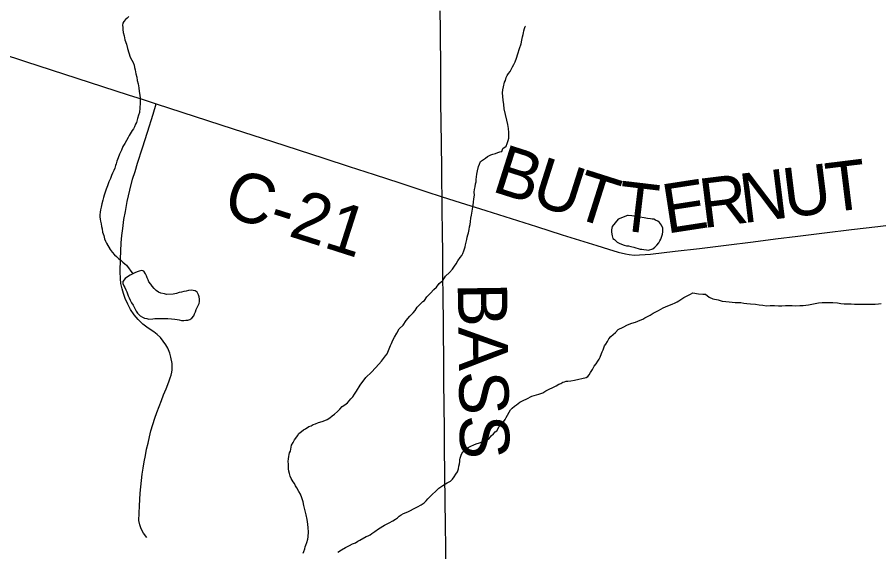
# Model space of a CAD drawing. Extents: x 103424 to 286016, y 38711 to 110967.
# Drawn here: x 139139 to 144407, y 67287 to 70553 of the extents above; entities that cross this region are included whole.
import ezdxf

# ---------------------------------------------------------------- set-up
doc = ezdxf.new("R2010")
doc.units = 0
for name, color, linetype in [('GM_X_County_Road', 7, 'Continuous'), ('GM_X_County_Road_Text', 7, 'Continuous'), ('GM_X_Minor_Lake', 7, 'Continuous'), ('GM_X_Minor_River', 7, 'Continuous'), ('GM_X_Township_Road', 7, 'Continuous')]:
    doc.layers.add(name, color=color, linetype=linetype)

msp = doc.modelspace()

# ---------------------------------------------------------------- linework, layer by layer
at = {"layer": 'GM_X_County_Road'}
for points in [[(141737, 69455.8), (141735.7, 69545.3), (141734.5, 69634.9), (141732.4, 69775.3), (141730.3, 69915.7), (141729.9, 70027.8), (141729.6, 70140), (141728.3, 70305), (141727.6, 70392.9), (141726.9, 70480.8), (141726, 70592.2)], [(139032.6, 70333.1), (139189.6, 70282.3), (139346.7, 70231.6), (139503.8, 70180.9), (139660.9, 70130.1), (139817.9, 70079.4), (139903.5, 70051.7), (139989, 70024.1), (140146.1, 69973.3), (140303.1, 69922.4), (140460.1, 69871.5), (140580.3, 69832.6), (140700.5, 69793.6), (140857.4, 69742.5), (141014.4, 69691.3), (141167.9, 69641.3), (141321.4, 69591.3), (141478.3, 69540.1), (141557.6, 69514.3), (141637, 69488.4), (141737, 69455.8), (141847.2, 69421.3), (142004.6, 69371.6), (142159.2, 69322.7), (142313.8, 69273.9), (142471.2, 69224.3), (142576.8, 69191), (142682.4, 69157.7), (142753.7, 69135.4), (142813.7, 69117.7), (142858, 69106.3), (142881.5, 69102.4), (142912, 69098.9), (143012.2, 69104.8), (143161.6, 69122.8), (143311, 69140.7), (143474.8, 69161.1), (143638.6, 69181.4), (143775.2, 69198.4), (143911.8, 69215.4), (144075.6, 69235.3), (144239.5, 69255.2), (144402.3, 69275), (144565.2, 69294.9)], [(141760.6, 67146.3), (141759, 67311.4), (141757.6, 67452.8), (141756.2, 67594.2), (141754.3, 67759.3), (141752.4, 67924.4), (141751, 68046.9), (141749.6, 68169.3), (141748.1, 68334.4), (141746.6, 68499.5), (141745.7, 68591.3), (141744.9, 68683.1), (141743.4, 68848.2), (141742.3, 68970.3), (141741.1, 69092.5), (141739.3, 69257.6), (141738.2, 69356.7), (141737, 69455.8)]]:
    msp.add_lwpolyline(points, dxfattribs=at)
at = {"layer": 'GM_X_Minor_Lake'}
for points in [[(142814.4, 69319.6), (142777, 69274.4), (142775.2, 69264.2), (142773.4, 69254.1), (142773.7, 69242), (142773.9, 69227.9), (142776.2, 69217.8), (142780.6, 69201.8), (142790.8, 69193.9), (142807.4, 69178.1), (142819.6, 69172.3), (142833.9, 69166.6), (142850.2, 69160.9), (142864.4, 69157.1), (142876.6, 69155.4), (142890.8, 69151.6), (142909.1, 69148), (142921.3, 69144.2), (142935.5, 69140.5), (142947.7, 69136.7), (142957.8, 69134.9), (142970, 69133.2), (142986.2, 69131.5), (142998.4, 69129.8), (143026.5, 69138.5), (143038.4, 69148.8), (143050.3, 69159.2), (143062.1, 69173.5), (143067.9, 69185.8), (143073.8, 69196), (143081.5, 69214.4), (143085.2, 69226.5), (143087, 69240.7), (143086.7, 69254.9), (143086.4, 69264.9), (143078, 69282.9), (143065.5, 69298.8), (143055.2, 69306.7), (143041, 69312.4), (143030.7, 69318.2), (143020.6, 69320), (143010.4, 69321.8), (142992.2, 69323.5), (142971.9, 69327.1), (142945.6, 69330.5), (142921.2, 69336), (142896.9, 69339.6), (142874.6, 69341.1), (142871.2, 69340.7)], [(142871.2, 69340.7), (142814.4, 69319.6)], [(140003, 68873.2), (139988.7, 68883.1), (139976.5, 68895), (139964.2, 68909), (139956, 68921), (139943.7, 68936.9), (139939.6, 68949), (139933.4, 68961), (139929.2, 68973), (139923, 68985.1), (139912.7, 69001.1), (139900.5, 69004.9), (139884.5, 69000.7), (139872.4, 68996.5), (139858.4, 68990.3), (139846.4, 68984.1), (139830.3, 68977.8), (139812.3, 68967.5), (139798.3, 68957.2), (139784.4, 68938.9), (139784.6, 68926.8), (139790.8, 68912.7), (139797, 68900.7), (139803.2, 68886.6), (139809.4, 68874.6), (139817.8, 68850.5), (139824, 68838.5), (139830.2, 68824.5), (139838.4, 68808.4), (139848.7, 68794.5), (139854.9, 68780.4), (139859.1, 68768.4), (139865.3, 68756.4), (139873.5, 68744.4), (139889.8, 68728.4), (139904, 68720.6), (139918.2, 68714.7), (139932.4, 68712.9), (139944.5, 68709), (139968.7, 68709.3), (139980.8, 68711.5), (140009, 68711.9), (140021.1, 68712), (140059.4, 68712.5), (140081.6, 68710.8), (140101.8, 68707), (140117.9, 68705.2), (140130.1, 68703.4), (140144.2, 68699.5), (140158.3, 68699.7), (140170.4, 68701.9), (140182.5, 68702.1)], [(140182.5, 68702.1), (140194.6, 68706.3), (140206.6, 68714.5), (140218.5, 68728.8), (140222.4, 68740.9), (140228.3, 68753.1), (140234.1, 68767.3), (140251.8, 68803.8), (140253.7, 68816), (140253.5, 68830.1), (140251.3, 68844.2), (140247.2, 68856.2), (140238.9, 68872.3), (140226.7, 68880.2), (140214.6, 68884), (140202.4, 68885.9), (140186.3, 68883.7), (140172.3, 68879.4), (140158.2, 68877.2), (140144.1, 68873), (140130, 68870.8), (140112, 68864.5), (140091.9, 68860.2), (140051.5, 68859.7), (140039.4, 68863.6), (140017.2, 68867.3), (140003, 68873.2)]]:
    msp.add_lwpolyline(points, dxfattribs=at)
at = {"layer": 'GM_X_Minor_River'}
for points in [[(139821, 70556.8), (139811.1, 70546.5), (139801.2, 70538.2), (139791.3, 70525.9), (139785.5, 70515.7), (139781.7, 70503.5), (139784, 70489.4), (139784.3, 70477.3), (139786.7, 70459.2), (139793.2, 70439.1), (139797.7, 70415), (139806.4, 70388.9), (139813, 70362.8), (139821.7, 70334.7), (139830.3, 70308.7), (139838.8, 70290.7), (139847.2, 70276.7), (139853.6, 70260.7), (139855.9, 70246.7), (139860.3, 70230.6), (139864.8, 70206.5), (139869.3, 70186.4), (139871.8, 70166.2), (139878.3, 70146.2), (139882.8, 70122), (139885.3, 70099.9), (139887.8, 70077.7), (139890.2, 70057.6), (139890.5, 70043.5), (139890.9, 70027.3), (139886, 69970.7), (139880.3, 69954.4), (139874.7, 69934.1), (139869.1, 69909.7), (139861.3, 69899.5), (139855.6, 69883.2), (139849.7, 69871), (139841.9, 69860.7), (139836, 69850.5), (139830.2, 69840.2), (139824.4, 69830), (139816.5, 69817.7), (139806.8, 69799.4), (139797.1, 69781), (139785.4, 69762.5), (139775.7, 69740.1), (139764.1, 69715.6), (139756.5, 69693.3), (139748.9, 69672.9), (139743.2, 69656.6), (139739.3, 69646.5), (139735.6, 69630.2), (139729.9, 69616), (139722.1, 69599.7), (139716.4, 69585.4), (139708.7, 69567), (139699, 69546.6), (139691.4, 69522.3), (139681.8, 69501.9), (139676.1, 69483.6), (139670.4, 69465.3), (139666.7, 69451), (139663, 69434.8), (139655.4, 69412.4), (139651.8, 69392.2), (139648.1, 69375.9), (139646.4, 69361.8)], [(142108.4, 70109.9), (142112, 70128.1), (142119.5, 70156.5), (142125.4, 70166.8), (142129, 70185), (142134.8, 70197.3), (142142.6, 70209.5), (142152.5, 70221.9), (142160.3, 70234.2), (142168, 70250.5), (142175.8, 70264.8), (142183.6, 70281.1), (142191.2, 70303.5), (142200.7, 70329.9), (142210.1, 70362.4), (142219.6, 70390.9), (142225.2, 70413.2), (142228.8, 70433.5), (142232.6, 70447.7), (142234.4, 70457.9), (142236.1, 70470), (142239.9, 70484.2), (142245.7, 70496.5), (142247.6, 70498.5)], [(141178.5, 68222), (141190.3, 68234.4), (141202.1, 68248.8), (141213.9, 68267.2), (141235.3, 68304), (141270.7, 68351.2), (141304.3, 68384.2), (141330, 68411), (141349.8, 68433.7), (141365.6, 68452.2), (141379.3, 68468.6), (141391.2, 68483), (141401, 68495.4), (141422.2, 68546.3), (141428, 68558.5), (141431.8, 68568.7), (141437.5, 68583), (141445.3, 68597.3), (141461, 68621.8), (141474.6, 68648.4), (141498.3, 68671.1), (141517.9, 68699.8), (141539.6, 68726.5), (141559.4, 68747.2), (141573.2, 68761.6), (141584.9, 68782), (141602.7, 68800.6), (141618.6, 68815.1), (141628.5, 68821.3), (141644.2, 68843.9), (141666, 68866.6), (141685.7, 68889.2), (141703.6, 68903.7), (141719.3, 68926.3), (141741.1, 68944.9), (141758.7, 68971.6), (141782.5, 68992.3), (141800.3, 69012.9), (141812, 69031.3), (141823.8, 69045.7), (141833.6, 69064.1), (141847.3, 69084.5), (141857.1, 69096.9), (141862.9, 69109.1), (141870.7, 69125.4), (141874.4, 69137.6), (141878.2, 69149.8), (141880, 69162), (141883.7, 69178.2), (141887.4, 69194.4), (141891.1, 69208.7), (141894.8, 69222.9), (141898.6, 69235.1), (141900.4, 69245.2), (141902.2, 69255.3), (141903.9, 69271.5), (141907.7, 69285.7), (141911.3, 69304), (141912.9, 69324.2), (141916.5, 69344.5), (141927.3, 69405.3), (141929, 69423.5), (141930.6, 69443.7), (141934.1, 69466), (141933.7, 69484.2), (141935.4, 69500.4), (141939.1, 69516.6), (141940.7, 69534.8), (141944.5, 69547), (141946.2, 69561.2), (141947.9, 69577.4), (141949.6, 69593.6), (141953.2, 69613.8), (141958.7, 69640.2), (141966.5, 69654.5), (141972.2, 69670.8), (141990.1, 69683.3), (142002.1, 69691.6), (142014, 69702), (142034, 69712.5), (142048, 69716.8), (142064.1, 69721.2), (142078.2, 69725.6), (142090.2, 69729.9), (142102.3, 69732.2), (142108, 69750.5), (142127.9, 69765), (142135.6, 69781.3), (142141.3, 69799.6), (142145, 69813.8), (142144.7, 69828), (142144.3, 69848.2), (142143.8, 69872.4), (142139.2, 69896.5), (142132.5, 69924.6), (142116.9, 69992.9), (142114.4, 70019.1), (142109.8, 70045.3), (142109.2, 70069.5), (142106.7, 70091.7), (142108.4, 70109.9)], [(139646.4, 69361.8), (139644.7, 69345.6), (139644.9, 69333.5), (139645.2, 69319.3), (139647.5, 69307.3), (139651.9, 69291.2), (139654.3, 69275.1), (139658.6, 69259.1), (139661.1, 69238.9), (139667.6, 69218.9), (139672.1, 69198.8), (139678.4, 69184.8), (139684.7, 69172.8), (139707.8, 69132.9), (139720.3, 69117), (139732.8, 69101.2), (139745.1, 69091.3), (139757.5, 69079.5), (139771.9, 69067.7), (139784.2, 69055.8), (139796.6, 69046), (139806.9, 69038.2), (139846.4, 68984.1)], [(142166, 68164.7), (142179.9, 68177.1), (142191.8, 68185.5), (142211.7, 68200), (142231.7, 68210.6), (142255.8, 68221.2), (142285.7, 68238), (142327.9, 68249), (142352, 68257.6), (142371.9, 68270.1), (142391.9, 68280.7), (142413.9, 68291.2), (142434, 68299.8), (142449.9, 68310.2), (142464, 68314.5), (142475.9, 68322.9), (142486, 68325.1), (142496, 68329.4), (142506.1, 68329.6), (142524.2, 68332), (142546.4, 68334.5), (142618.8, 68352.2), (142628.8, 68358.5), (142636.6, 68368.8), (142644.4, 68383.1), (142656.2, 68399.5), (142665.9, 68419.9), (142679.7, 68434.3), (142689.5, 68450.7), (142697.3, 68463), (142703.1, 68475.2), (142712.7, 68497.6), (142716.5, 68507.8), (142722.3, 68520.1), (142726.1, 68532.2), (142729.9, 68544.4), (142737.8, 68554.7), (142747.5, 68571.1), (142757.3, 68587.4), (142769.1, 68601.8), (142783, 68614.2), (142796.9, 68626.7), (142812.6, 68645.2), (142844.7, 68660), (142870.7, 68672.7), (142896.7, 68683.3), (142918.8, 68689.9), (142934.8, 68696.3), (142948.9, 68702.7), (142964.9, 68707), (142976.9, 68715.4), (142992.9, 68723.8), (143008.9, 68732.2), (143026.8, 68744.7), (143060.8, 68761.6), (143088.8, 68776.4), (143116.8, 68789.1), (143142.8, 68799.8), (143162.9, 68808.3), (143174.9, 68814.6), (143184.8, 68820.9), (143202.8, 68831.3), (143214.7, 68839.7), (143256.7, 68860.8), (143270.7, 68869.2), (143305.2, 68861.8), (143331.5, 68860.4), (143347.7, 68860.7), (143370.3, 68843.1), (143392.8, 68831.4), (143425.2, 68826.1), (143449.7, 68818.5), (143472, 68815), (143492.2, 68813.4), (143510.4, 68811.8), (143528.7, 68810.2), (143546.8, 68810.6), (143563, 68808.9), (143581.3, 68805.2), (143599.5, 68803.6), (143621.8, 68802.1), (143654.2, 68798.8), (143676.5, 68795.2), (143698.8, 68793.7), (143721.1, 68790.1), (143743.3, 68790.6), (143769.6, 68791.2), (143793.9, 68789.7), (143814.1, 68790.1), (143836.3, 68790.6), (143856.5, 68791), (143876.7, 68791.5), (143896.9, 68789.9), (143925.2, 68790.5), (143945.4, 68791), (143961.5, 68793.3), (143977.7, 68795.7), (144038.1, 68807.1), (144060.2, 68809.6), (144080.4, 68810), (144102.7, 68810.5)], [(144102.7, 68810.5), (144126.9, 68809), (144155.3, 68807.6), (144175.6, 68804), (144195.8, 68802.5), (144218.1, 68800.9), (144238.3, 68801.4), (144258.5, 68799.8), (144282.8, 68800.3), (144303, 68798.7), (144325.2, 68799.2), (144347.5, 68799.7), (144367.7, 68800.1), (144385.8, 68800.5), (144406, 68801), (144422.2, 68803.3)], [(140887.3, 67278.8), (140891.1, 67289), (140896.8, 67305.3), (140900.6, 67317.5), (140904.4, 67327.6), (140910.1, 67343.9), (140915.8, 67364.2), (140917.5, 67378.4), (140920.9, 67408.7), (140918.4, 67432.9), (140915.9, 67455.1), (140911.2, 67483.2), (140906.6, 67511.4), (140900, 67537.5), (140895.6, 67553.6), (140891.2, 67569.6), (140886.7, 67591.7), (140880.1, 67615.8), (140871.5, 67637.9), (140861.1, 67655.8), (140848.5, 67677.7), (140840.1, 67689.7), (140833.8, 67703.7), (140825.5, 67713.6), (140814.9, 67733.5), (140808.5, 67749.5), (140804.1, 67765.6), (140799.8, 67779.6), (140797.5, 67793.7), (140797.1, 67809.9), (140796.9, 67822), (140796.5, 67838.1), (140798.2, 67854.3), (140799.9, 67868.5), (140801.7, 67880.6), (140803.5, 67890.8), (140809.4, 67901), (140816.6, 67937.5), (140826.4, 67953.9), (140834.1, 67970.2), (140842, 67980.5), (140851.8, 67994.8), (140861.6, 68009.1), (140877.5, 68021.6), (140889.4, 68032), (140901.4, 68038.3), (140921.3, 68052.8), (140935.4, 68057.2), (140949.4, 68063.6), (140963.4, 68067.9), (140981.5, 68076.4), (141003.5, 68082.9), (141019.6, 68089.3), (141033.6, 68095.7), (141049.5, 68106.1), (141065.5, 68116.6), (141079.4, 68127), (141097.2, 68143.5), (141111.1, 68157.9), (141126.9, 68174.4), (141142.9, 68184.9), (141158.8, 68197.3), (141168.6, 68209.7), (141178.5, 68222)], [(141099.4, 67283.4), (141121.3, 67298), (141147.3, 67312.7), (141171.3, 67325.4), (141189.2, 67335.8), (141207.3, 67342.3), (141221.3, 67350.7), (141233.3, 67357), (141273.2, 67380.1), (141285.2, 67384.4), (141297.2, 67390.7), (141307.2, 67399), (141325.1, 67411.5), (141349, 67426.1), (141384.9, 67449.1), (141412.9, 67463.9), (141434.9, 67476.5), (141452.8, 67486.9), (141464.8, 67493.3), (141474.7, 67503.6), (141486.7, 67511.9), (141500.6, 67520.3), (141516.6, 67526.7), (141530.7, 67533.1), (141544.7, 67539.4), (141562.6, 67549.9), (141586.7, 67560.5), (141608.6, 67573.1), (141626.6, 67585.6), (141640.4, 67598), (141650.3, 67610.4), (141664.1, 67624.8), (141676, 67637.2), (141697.8, 67657.8), (141717.6, 67674.4), (141741.5, 67691.1), (141767.5, 67707.8), (141787.4, 67718.3), (141801.3, 67730.8), (141811.1, 67745.1), (141820.9, 67761.5), (141830.7, 67775.8), (141836.4, 67794.1), (141840.1, 67810.3), (141843.8, 67824.6), (141845.5, 67838.7), (141845.3, 67848.8), (141847.1, 67858.9), (141850.9, 67871.1), (141854.7, 67883.3), (141864.5, 67897.7), (141896.2, 67924.6), (141912.3, 67931), (141930.3, 67939.5), (141946.3, 67945.9), (141966.4, 67952.4), (141982.4, 67958.8), (141998.5, 67965.2), (142012.5, 67971.6), (142024.5, 67977.9), (142036.2, 67994.3), (142052.1, 68006.8), (142062, 68019.1), (142072, 68025.4), (142085.5, 68051.9), (142101.3, 68070.4), (142113.2, 68080.8), (142123, 68095.1), (142128.8, 68107.4), (142136.6, 68121.7), (142146.3, 68140.1), (142156.1, 68154.4), (142166, 68164.7)]]:
    msp.add_lwpolyline(points, dxfattribs=at)
at = {"layer": 'GM_X_Township_Road'}
msp.add_lwpolyline([(139930.9, 67374.8), (139911.2, 67400.8), (139897.2, 67426.3), (139889, 67450.4), (139883.3, 67478.4), (139885.6, 67566.8), (139887.7, 67605.6), (139890.5, 67644.3), (139894, 67682.9), (139898, 67721.5), (139903.1, 67760), (139908.9, 67798.4), (139915.2, 67836.6), (139922.5, 67874.8), (139930.4, 67912.8), (139938.9, 67950.6), (139947.7, 67988.2), (139956.6, 68025.1), (139968, 68065.2), (139980.7, 68103.3), (139992.8, 68138.3), (140006, 68173.5), (140020.4, 68210.6), (140034, 68245.9), (140049.1, 68281.7), (140066.7, 68325.8), (140075, 68349.7), (140080.6, 68366.7), (140084.7, 68383.7), (140086.4, 68397.5), (140087.2, 68411.4), (140085.7, 68437.2), (140079.1, 68475.8), (140072.2, 68500.2), (140059.9, 68529.9), (140048.1, 68551.3), (140031.6, 68574), (140014.4, 68595), (139995.4, 68613.4), (139974, 68629.6), (139938.8, 68653.5), (139907.6, 68678.3), (139879, 68706.3), (139854.2, 68734.9), (139832.5, 68767.3), (139814.7, 68800.4), (139799.5, 68834.1), (139788, 68864.7), (139779.8, 68893.3), (139773.4, 68926.4), (139769.6, 68956.9), (139767.7, 68996.9), (139769.6, 69076.5), (139771.5, 69122.9), (139774, 69174.4), (139778.5, 69220.2), (139784.2, 69261.5), (139791.8, 69316.9), (139800.1, 69366.5), (139811.5, 69426.3), (139826.8, 69495.6), (139844.6, 69563), (139859.2, 69611.3), (139874.5, 69661), (139905.1, 69755.7), (139935.6, 69850.5), (139970.6, 69961.2), (139989, 70024.1)], dxfattribs=at)

# ---------------------------------------------------------------- texts
at = {"layer": 'GM_X_County_Road_Text'}
for s, height, rotation, p in [('B', 301.9, 342.35, (142032.9, 69492)), ('U', 301.9, 342.3496, (142269.2, 69416.8)), ('U', 301.9, 7.0466, (143839.8, 69326.7)), ('T', 301.9, 7.0463, (144103.4, 69359.3)), ('C-21', 301.87, 342.2153, (140384.5, 69348.6)), ('T', 301.9, 342.3938, (142522.5, 69336.2)), ('N', 301.9, 7.0446, (143576.1, 69294.1)), ('T', 301.9, 353.2115, (142797.5, 69254.9)), ('E', 301.9, 8.7349, (143109.2, 69229.8)), ('R', 301.9, 7.0471, (143330.1, 69263.7)), ('BASS', 301.87, 270.8259, (141832.3, 68928.8))]:
    msp.add_text(s, height=height, rotation=rotation, dxfattribs=at).set_placement(p)

doc.saveas('drawing.dxf')
